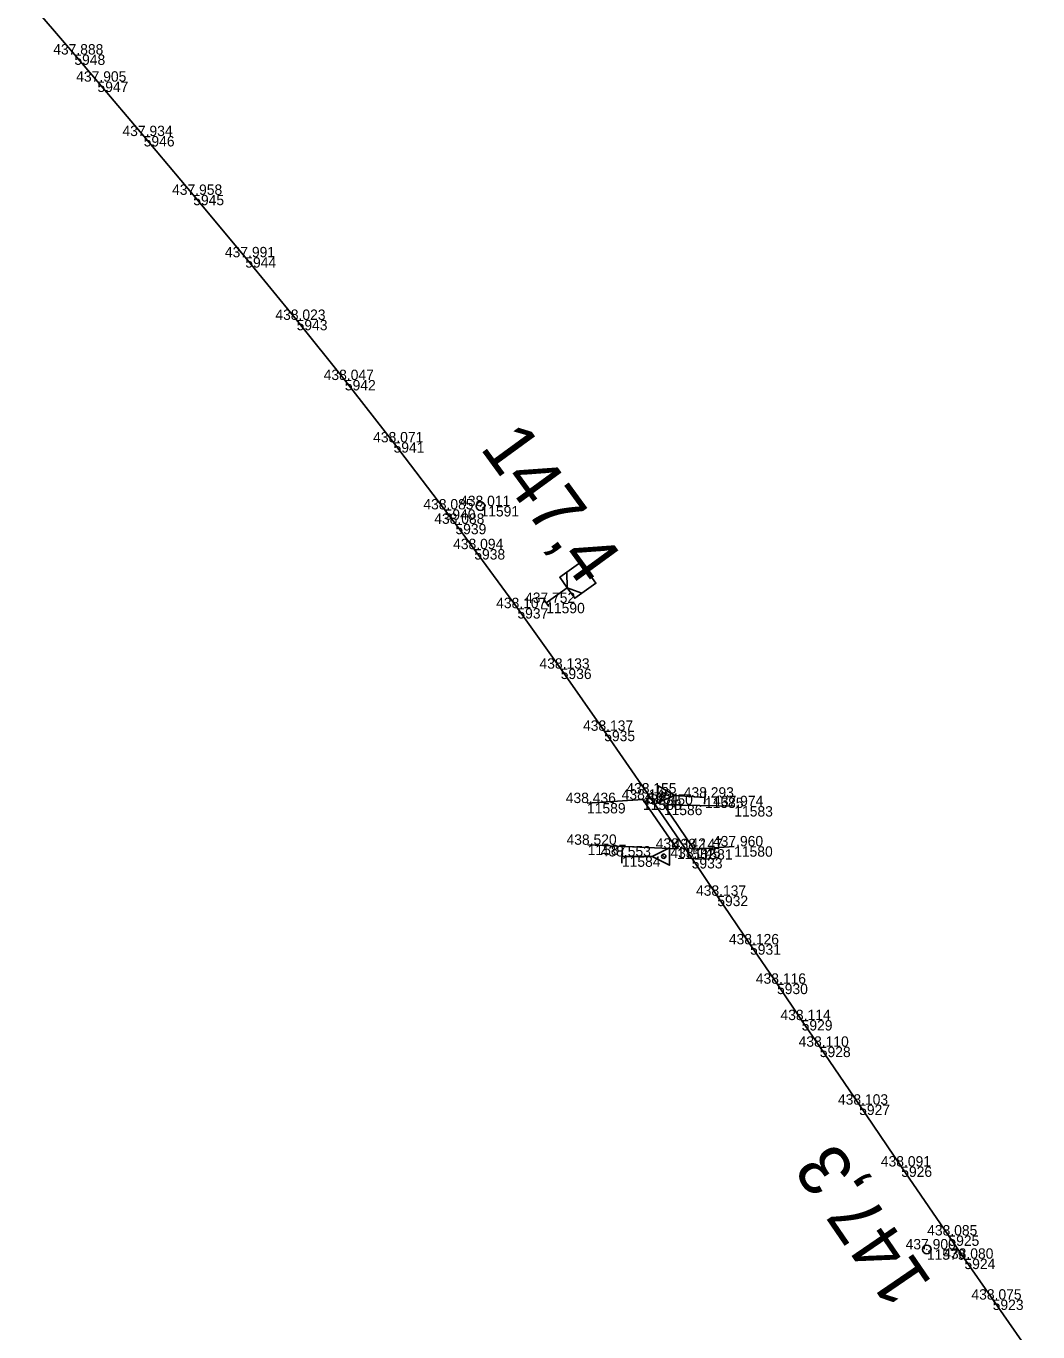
# Model space of a CAD drawing. Extents: x -654154 to -652650, y -1166925 to -1164904.
# Drawn here: x -653895.9 to -653778.9, y -1165360.8 to -1165209.7 of the extents above; entities that cross this region are included whole.
import ezdxf

# ---------------------------------------------------------------- set-up
doc = ezdxf.new("R2010")
doc.units = 0
for name, color, linetype in [('Vrstva 1', 7, 'Continuous'), ('Vrstva 4', 7, 'Continuous'), ('Vrstva 51', 7, 'Continuous'), ('Vrstva 60', 7, 'Continuous'), ('Vrstva 61', 7, 'Continuous'), ('Vrstva 7', 7, 'Continuous')]:
    doc.layers.add(name, color=color, linetype=linetype)

msp = doc.modelspace()

# ---------------------------------------------------------------- linework, layer by layer
at = {"layer": 'Vrstva 1'}
msp.add_lwpolyline([(-653778.89, -1165364.57), (-653784.12, -1165357.1), (-653787.39, -1165352.37), (-653789.24, -1165349.68), (-653794.7, -1165341.7), (-653799.57, -1165334.54), (-653804.12, -1165327.84), (-653806.22, -1165324.76), (-653809.07, -1165320.55), (-653812.19, -1165315.99), (-653815.98, -1165310.37), (-653818.94, -1165306.01), (-653824.05, -1165298.53), (-653829.06, -1165291.28), (-653834.09, -1165284.09), (-653839.1, -1165277.09), (-653844.09, -1165270.26), (-653846.27, -1165267.33), (-653847.52, -1165265.66), (-653853.43, -1165257.9), (-653859.06, -1165250.69), (-653864.64, -1165243.73), (-653870.58, -1165236.48), (-653876.6, -1165229.26), (-653882.33, -1165222.46), (-653887.68, -1165216.16), (-653890.35, -1165213.02), (-653895.93, -1165206.45)], dxfattribs=at)
at = {"layer": 'Vrstva 4'}
for p, q in [((-653822.08, -1165298.9), (-653822.4, -1165298.53)), ((-653817.46, -1165299.78), (-653817.35, -1165298.23)), ((-653827, -1165305.04), (-653827.01, -1165306.6)), ((-653822.34, -1165305.62), (-653821.99, -1165305.97))]:
    msp.add_line(p, q, dxfattribs=at)
for points in [[(-653817.41, -1165299.01), (-653820.88, -1165298.77), (-653822.94, -1165299.62), (-653822.81, -1165297.63), (-653820.88, -1165298.77)], [(-653827.01, -1165305.82), (-653823.53, -1165305.82), (-653821.52, -1165304.84), (-653821.52, -1165306.83), (-653823.53, -1165305.82)]]:
    msp.add_lwpolyline(points, dxfattribs=at)
for centre in [(-653822.24, -1165298.71), (-653822.17, -1165305.79)]:
    msp.add_circle(centre, 0.248, dxfattribs=at)
at = {"layer": 'Vrstva 51'}
for points in [[(-653831.05, -1165299.64), (-653824.58, -1165299.24), (-653820.65, -1165304.92), (-653830.97, -1165304.47)], [(-653814.01, -1165300), (-653822.16, -1165299.84), (-653818.68, -1165304.98), (-653814.03, -1165304.65)]]:
    msp.add_lwpolyline(points, dxfattribs=at)
at = {"layer": 'Vrstva 60'}
for p, q in [((-653890.35, -1165213.02), (-653890.35, -1165213.02)), ((-653887.68, -1165216.16), (-653887.68, -1165216.16)), ((-653882.33, -1165222.46), (-653882.33, -1165222.46)), ((-653876.6, -1165229.26), (-653876.6, -1165229.26)), ((-653870.58, -1165236.48), (-653870.58, -1165236.48)), ((-653864.64, -1165243.73), (-653864.64, -1165243.73)), ((-653859.06, -1165250.69), (-653859.06, -1165250.69)), ((-653853.43, -1165257.9), (-653853.43, -1165257.9)), ((-653843.37, -1165265.28), (-653843.37, -1165265.28)), ((-653847.52, -1165265.66), (-653847.52, -1165265.66)), ((-653846.27, -1165267.33), (-653846.27, -1165267.33)), ((-653844.09, -1165270.26), (-653844.09, -1165270.26)), ((-653839.1, -1165277.09), (-653839.1, -1165277.09)), ((-653835.77, -1165276.48), (-653835.77, -1165276.48)), ((-653834.09, -1165284.09), (-653834.09, -1165284.09)), ((-653829.06, -1165291.28), (-653829.06, -1165291.28)), ((-653824.05, -1165298.53), (-653824.05, -1165298.53)), ((-653831.05, -1165299.64), (-653831.05, -1165299.64)), ((-653824.58, -1165299.24), (-653824.58, -1165299.24)), ((-653822.16, -1165299.84), (-653822.16, -1165299.84)), ((-653817.41, -1165299.01), (-653817.41, -1165299.01)), ((-653814.01, -1165300), (-653814.01, -1165300)), ((-653830.97, -1165304.47), (-653830.97, -1165304.47)), ((-653814.03, -1165304.65), (-653814.03, -1165304.65)), ((-653827.01, -1165305.82), (-653827.01, -1165305.82)), ((-653820.65, -1165304.92), (-653820.65, -1165304.92)), ((-653818.94, -1165306.01), (-653818.94, -1165306.01)), ((-653818.68, -1165304.98), (-653818.68, -1165304.98)), ((-653815.98, -1165310.37), (-653815.98, -1165310.37)), ((-653812.19, -1165315.99), (-653812.19, -1165315.99)), ((-653809.07, -1165320.55), (-653809.07, -1165320.55)), ((-653806.22, -1165324.76), (-653806.22, -1165324.76)), ((-653804.12, -1165327.84), (-653804.12, -1165327.84)), ((-653799.57, -1165334.54), (-653799.57, -1165334.54)), ((-653794.7, -1165341.7), (-653794.7, -1165341.7)), ((-653789.24, -1165349.68), (-653789.24, -1165349.68)), ((-653791.74, -1165351.29), (-653791.74, -1165351.29)), ((-653787.39, -1165352.37), (-653787.39, -1165352.37)), ((-653784.12, -1165357.1), (-653784.12, -1165357.1))]:
    msp.add_line(p, q, dxfattribs=at)
at = {"layer": 'Vrstva 7'}
for p, q in [((-653843.4, -1165265.23), (-653843.34, -1165265.32)), ((-653833.33, -1165274.73), (-653835.77, -1165276.48)), ((-653836.06, -1165276.07), (-653835.48, -1165276.88)), ((-653791.71, -1165351.33), (-653791.76, -1165351.25))]:
    msp.add_line(p, q, dxfattribs=at)
for points in [[(-653833.33, -1165274.73), (-653832.46, -1165275.95), (-653830.02, -1165274.21), (-653831.76, -1165271.77), (-653834.2, -1165273.51), (-653833.33, -1165274.73)], [(-653833.39, -1165272.93), (-653833.33, -1165274.73), (-653831.64, -1165275.37)]]:
    msp.add_lwpolyline(points, dxfattribs=at)
for centre in [(-653843.37, -1165265.28), (-653791.74, -1165351.29)]:
    msp.add_circle(centre, 0.5, dxfattribs=at)

# ---------------------------------------------------------------- texts
at = {"layer": 'Vrstva 60'}
for s, p in [('5948', (-653890.35, -1165214.22)), ('5947', (-653887.68, -1165217.36)), ('5946', (-653882.33, -1165223.66)), ('5945', (-653876.6, -1165230.46)), ('5944', (-653870.58, -1165237.68)), ('5943', (-653864.64, -1165244.93)), ('5942', (-653859.06, -1165251.89)), ('5941', (-653853.43, -1165259.09)), ('11591', (-653843.37, -1165266.48)), ('5940', (-653847.52, -1165266.86)), ('5939', (-653846.27, -1165268.53)), ('5938', (-653844.09, -1165271.46)), ('5937', (-653839.1, -1165278.29)), ('11590', (-653835.77, -1165277.68)), ('5936', (-653834.09, -1165285.29)), ('5935', (-653829.06, -1165292.48)), ('5934', (-653824.05, -1165299.73)), ('11589', (-653831.05, -1165300.84)), ('11588', (-653824.58, -1165300.44)), ('11586', (-653822.16, -1165301.04)), ('11585', (-653817.41, -1165300.21)), ('11583', (-653814.01, -1165301.2)), ('11587', (-653830.97, -1165305.67)), ('11580', (-653814.03, -1165305.85)), ('11584', (-653827.01, -1165307.02)), ('11582', (-653820.65, -1165306.12)), ('5933', (-653818.94, -1165307.21)), ('11581', (-653818.68, -1165306.18)), ('5932', (-653815.98, -1165311.57)), ('5931', (-653812.19, -1165317.19)), ('5930', (-653809.07, -1165321.75)), ('5929', (-653806.22, -1165325.96)), ('5928', (-653804.12, -1165329.04)), ('5927', (-653799.57, -1165335.74)), ('5926', (-653794.7, -1165342.9)), ('5925', (-653789.24, -1165350.88)), ('11579', (-653791.74, -1165352.49)), ('5924', (-653787.39, -1165353.57)), ('5923', (-653784.12, -1165358.3))]:
    msp.add_text(s, height=1.2, dxfattribs=at).set_placement(p)
at = {"layer": 'Vrstva 61'}
for s, p in [('437.888', (-653892.8, -1165213.02)), ('437.905', (-653890.14, -1165216.16)), ('437.934', (-653884.79, -1165222.46)), ('437.958', (-653879.05, -1165229.26)), ('437.991', (-653872.94, -1165236.48)), ('438.023', (-653867.1, -1165243.73)), ('438.047', (-653861.51, -1165250.69)), ('438.071', (-653855.79, -1165257.9)), ('438.085', (-653849.98, -1165265.66)), ('438.011', (-653845.73, -1165265.28)), ('438.088', (-653848.72, -1165267.33)), ('438.094', (-653846.54, -1165270.26)), ('438.107', (-653841.56, -1165277.09)), ('437.752', (-653838.22, -1165276.48)), ('438.133', (-653836.55, -1165284.09)), ('438.137', (-653831.51, -1165291.28)), ('438.436', (-653833.51, -1165299.64)), ('438.149', (-653827.04, -1165299.24)), ('438.155', (-653826.5, -1165298.53)), ('438.150', (-653824.61, -1165299.84)), ('438.293', (-653819.86, -1165299.01)), ('437.974', (-653816.46, -1165300)), ('438.520', (-653833.42, -1165304.47)), ('438.553', (-653829.46, -1165305.82)), ('438.142', (-653823.1, -1165304.92)), ('438.147', (-653821.13, -1165304.98)), ('437.960', (-653816.48, -1165304.65)), ('438.145', (-653821.4, -1165306.01)), ('438.137', (-653818.44, -1165310.37)), ('438.126', (-653814.64, -1165315.99)), ('438.116', (-653811.52, -1165320.55)), ('438.114', (-653808.67, -1165324.76)), ('438.110', (-653806.57, -1165327.84)), ('438.103', (-653802.02, -1165334.54)), ('438.091', (-653797.06, -1165341.7)), ('438.085', (-653791.7, -1165349.68)), ('437.900', (-653794.19, -1165351.29)), ('438.080', (-653789.84, -1165352.37)), ('438.075', (-653786.58, -1165357.1))]:
    msp.add_text(s, height=1.2, dxfattribs=at).set_placement(p)
at = {"layer": 'Vrstva 7'}
for s, rotation, p in [('147,4', 306.119, (-653843.51, -1165258.54)), ('147,3', 124.3706, (-653791.03, -1165355.2))]:
    msp.add_text(s, height=6, rotation=rotation, dxfattribs=at).set_placement(p)

doc.saveas('drawing.dxf')
